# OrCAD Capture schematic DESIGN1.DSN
size A0
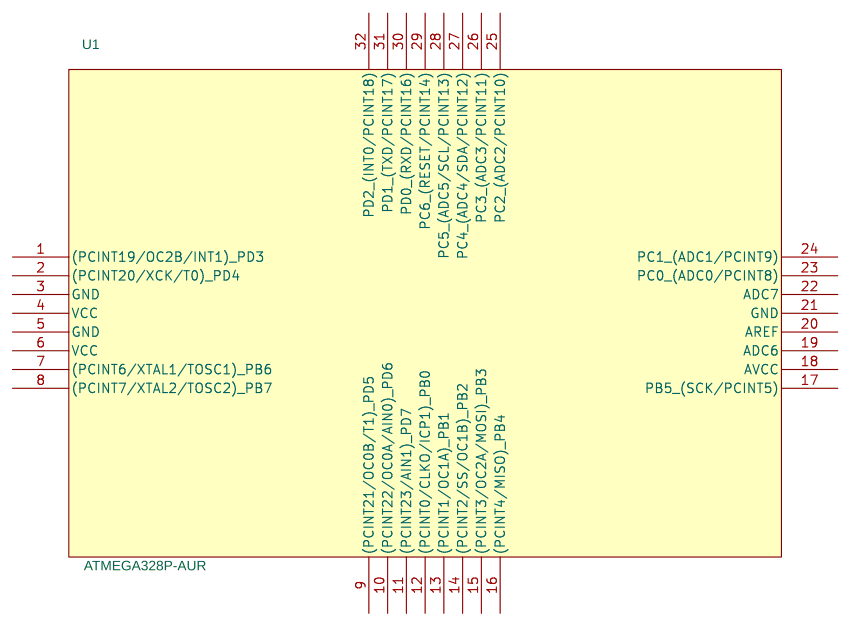
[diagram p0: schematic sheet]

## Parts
U1  ATMEGA328P-AUR  [TQFP_P080W050L700T700H120Q32]

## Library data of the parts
U1 = IC_ATMEGA328P-AUR

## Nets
AVCC: U1.18(AVCC)
GND: U1.3(GND) U1.5(GND) U1.21(GND)
VCC: U1.4(VCC) U1.6(VCC)
ADC6: U1.19(ADC6)
ADC7: U1.22(ADC7)
AREF: U1.20(AREF)

Not connected (* = marked no-connect by the designer): U1 1((PCINT19/OC2B/INT1)_PD3) 2((PCINT20/XCK/T0)_PD4) 7((PCINT6/XTAL1/TOSC1)_PB6) 8((PCINT7/XTAL2/TOSC2)_PB7) 9((PCINT21/OC0B/T1)_PD5) 10((PCINT22/OC0A/AIN0)_PD6) 11((PCINT23/AIN1)_PD7) 12((PCINT0/CLKO/ICP1)_PB0) 13((PCINT1/OC1A)_PB1) 14((PCINT2/SS/OC1B)_PB2) 15((PCINT3/OC2A/MOSI)_PB3) 16((PCINT4/MISO)_PB4) 17(PB5_(SCK/PCINT5)) 23(PC0_(ADC0/PCINT8)) 24(PC1_(ADC1/PCINT9)) 25(PC2_(ADC2/PCINT10)) 26(PC3_(ADC3/PCINT11)) 27(PC4_(ADC4/SDA/PCINT12)) 28(PC5_(ADC5/SCL/PCINT13)) 29(PC6_(RESET/PCINT14)) 30(PD0_(RXD/PCINT16)) 31(PD1_(TXD/PCINT17)) 32(PD2_(INT0/PCINT18))
